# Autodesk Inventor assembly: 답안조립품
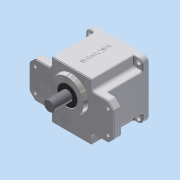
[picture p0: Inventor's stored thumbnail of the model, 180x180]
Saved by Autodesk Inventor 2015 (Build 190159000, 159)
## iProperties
Created: 2016-02
Part Number: 답안조립품
Document SubType Name: Assembly
Designer: Administrator
Author: Administrator
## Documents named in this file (10)
- C:\Users\Administrator\Desktop\460209V1001\답안조립품.iam
- C:\Users\Administrator\Desktop\460209V1001\본체.ipt
- C:\Users\Administrator\Desktop\460209V1001\커버.ipt
- C:\Users\Administrator\Desktop\460209V1001\볼트 M4 x 10.ipt
- C:\Users\Administrator\Desktop\460209V1001\오일실 8 22 7.ipt
- C:\Users\Administrator\Desktop\460209V1001\오일실 17 32 8.ipt
- C:\Users\Administrator\Desktop\460209V1001\베어링 608.ipt
- C:\Users\Administrator\Desktop\460209V1001\서브축.ipt
- C:\Users\Administrator\Desktop\460209V1001\베어링 6003.ipt
- C:\Users\Administrator\Desktop\460209V1001\메인축.ipt
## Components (2 placed, 1 different names)
1. ISO 4762 M4 x 10:1 — Insert:1
2. ISO 4762 M4 x 10:2 — Insert:2
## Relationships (2: Insert 2)
- Insert:1: ISO 4762 M4 x 10:1
- Insert:2: ISO 4762 M4 x 10:2
